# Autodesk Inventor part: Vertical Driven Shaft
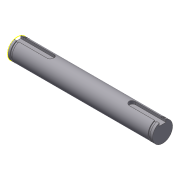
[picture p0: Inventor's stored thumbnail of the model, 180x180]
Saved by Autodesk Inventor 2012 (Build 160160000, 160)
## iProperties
Created: 2012-12
Part Number: Vertical Driven Shaft
Material: Aluminum-6061
Document SubType Name: Modeling
Designer: Owner
Density: 2.71 g/cm^3
Mass: 13.3113 g
Surface Area: 22.5658 cm^2
Volume: 4.91193 cm^3
Author: Owner
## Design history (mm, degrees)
sketch "Sketch1"
  geometry: L1 (0, 0)-(0, 4.763); L2 (0, 4.763)-(1.219, 4.763); L3 (1.219, 4.763)-(1.219, 4.356); L4 (1.219, 4.356)-(2.235, 4.356); L5 (2.235, 4.356)-(2.235, 4.763); L6 (2.235, 4.763)-(67.031, 4.763); L7 (67.031, 4.763)-(67.031, 4.356); L8 (67.031, 4.356)-(68.047, 4.356); L9 (68.047, 4.356)-(68.047, 4.763); L10 (68.047, 4.763)-(69.266, 4.763); L11 (69.266, 4.763)-(69.266, 0); L12 (69.266, 0)-(0, 0)
  constraints: 24 end point, 8 parallel, 5 collinear, 1 perpendicular, 1 vertical
  dimensions: "d0" = 9.525 diameter of L2 L12; "d1" = 8.7122 diameter of L4 L12; "d2" = 1.016 distance of L3.end L4.end; "d3" = 64.7954 distance of L5.end L6.end; "d4" = 1.2192 distance of L1.end L2.end; "d5" = 1.2192 distance of L9.end L10.end; "d6" = 1.016 distance of L7.end L8.end
revolve "Revolution1" sketch "Sketch1" stored, may be unused: angle "d7" = 90 deg
sketch "Sketch2"
  geometry: L1 (-3.707, 0)-(3.707, 0); L2 (-3.863, 1.449)-(3.863, 1.449); L3 (3.863, 1.449)-(3.863, -1.449); L4 (3.863, -1.449)-(-3.863, -1.449); L5 (-3.863, -1.449)-(-3.863, 1.449); L6 (0, 1.449)-(0, -1.449); C1 r 4.763 at (0, 0) reference; 1 further point
  constraints: 4 end point, 4 midpoint, 1 coincident, 1 horizontal, 2 other
sketch "Sketch3"
  geometry: L1 (-1.587, 6.35)-(1.587, 6.35); L2 (1.587, 6.35)-(1.587, 3.175); L3 (1.587, 3.175)-(-1.587, 3.175); L4 (-1.587, 3.175)-(-1.587, 6.35); L5 (0, 0)-(0, 3.175); 1 further point
  constraints: 11 end point, 2 parallel, 1 horizontal, 1 midpoint, 1 perpendicular, 1 point on line, 1 vertical, 1 vertical alignment, 1 other
  dimensions: "d8" = 7.9375 distance from line of L3 point (0, -4.762); "d9" = 3.175 distance of L1.start L1.end; "d10" = 3.175 distance of L3.end L1.start
extrude "Extrusion1" cut sketch "Sketch3" distance "d11" = 15.9639; taper "d12" = 0 deg
sketch "Sketch4"
  geometry: L1 (-1.588, 6.35)-(1.587, 6.35); L2 (1.587, 6.35)-(1.587, 3.175); L3 (1.587, 3.175)-(-1.587, 3.175); L4 (-1.587, 3.175)-(-1.588, 6.35); L5 (0, 3.175)-(0, -4.763); L6 (-1.587, -3.175)-(1.588, -3.175); L7 (1.588, -3.175)-(1.588, -6.35); L8 (1.588, -6.35)-(-1.587, -6.35); L9 (-1.587, -6.35)-(-1.587, -3.175); L10 (0, 4.763)-(0, -3.175); A1 r 4.763 centre (0, 0) between (0, -4.763) and (0, 4.763) reference
  constraints: 20 end point, 4 parallel, 2 horizontal, 2 midpoint, 2 perpendicular, 2 point on circle, 2 point on line, 2 vertical
  dimensions: "d13" = 7.9375 distance of L5.start L5.end; "d14" = 3.175 distance of L1.start L1.end; "d15" = 3.175 distance of L3.end L1.start; "d19" = 3.175 distance of L6.end L7.end; "d20" = 3.175 distance of L7.end L8.end; "d21" = 7.9375 distance of L10.start L10.end
extrude "Extrusion2" cut sketch "Sketch4" distance "d16" = 17.5387; taper "d17" = 0 deg
fillet "Fillet1" dims "d18" = 1.5875
body "Solid1"
